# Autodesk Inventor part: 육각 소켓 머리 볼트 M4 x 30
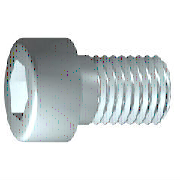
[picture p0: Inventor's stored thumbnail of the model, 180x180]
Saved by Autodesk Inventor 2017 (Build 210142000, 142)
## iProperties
IsCustomPart: 1
Created: 2012-02
Part Number: 육각 소켓 머리 볼트 M4 x 30
Material: 강철, 연강
Description: 원통형 머리 캡 나사
Document SubType Name: Modeling
Standard: JIS B 1176
Designer: mdu-01
Standards Organization: JIS
Language: ko-KR
Size Designation: M4 x 30
Categories: <MemberInstance><Categories><Category DisplayName="조임쇠" InternalName="e4da775c-781d-43d5-af7c-5136215cf5a6" Mnemonic="FSTN"><Category DisplayName="볼트" InternalN
Density: 1 g/cm^3
Appearance: 강철
Author: mdu-01
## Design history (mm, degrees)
sketch "스케치1"
  geometry: L1 (-1, 0)-(30, 0); L2 (30, 0)-(30, 2); L3 (30, 2)-(10, 2); L4 (10, 2)-(9.57, 2); L5 (9.57, 2)-(0, 2); L6 (0, 2)-(0, 3.5); L7 (0, 3.5)-(-4, 3.5); L8 (-4, 3.5)-(-4, 1.732); L9 (-4, 1.732)-(-2, 1.732); L10 (-2, 1.732)-(-1, 0); L11 (-10.8, 0)-(36.8, 0) reference; L12 (0, -0.7)-(0, 4.2) reference; L13 (10, 2)-(0, 2)
  constraints: 22 end point, 6 parallel, 2 collinear, 2 perpendicular, 1 horizontal, 1 point on line
  dimensions: "d1" = 20 distance from line of L3.end L2 (= GEL); "d2" = 0.42952 distance of L4.end L3.end (computed from GAL); "d3" = 4 distance between parallel lines of L8 L6 (= KOH); "d4" = 2 distance of L8.end L9.end (= INTI); "d5" = 60 deg angle of L10 L1; "d6" = 4 diameter of L3 L1 (= GD); "d7" = 4 diameter of L5 L1 (= BDM); "d8" = 3.4641 diameter of L9 L1 (= 1.1547 x SW); "d9" = 7 diameter of L7 L1 (= KOD); "d26" = 30 distance between parallel lines of L12 L2 (= NLG)
revolve "본체" sketch "스케치1" stored, may be unused: angle "d10" = 90 deg
sketch "스케치2"
  geometry: L1 (0, -4.9)-(0, 4.9) reference; L2 (-4.9, 0)-(4.9, 0) reference; L3 (1.732, 0)-(0.866, -1.5); L4 (0.866, -1.5)-(-0.866, -1.5); L5 (-0.866, -1.5)-(-1.732, 0); L6 (-1.732, 0)-(-0.866, 1.5); L7 (-0.866, 1.5)-(0.866, 1.5); L8 (0.866, 1.5)-(1.732, 0); 2 further points
  constraints: 12 end point, 1 coincident, 1 horizontal alignment, 1 point on line, 12 other
extrude "슬롯" join sketch "스케치2" stored distance "d11" = 10; taper "d12" = 0 deg
workplane "Work Plane1"
fillet "Fillet2" dims "d30" = 0.1 (= R)
body "Solid1"
fillet "모깎기1" dims "d17" = 0.4 (= RR)
feature "스레드" dims "d13" = 20 (= GEL), "d14" = 0
chamfer "모따기1" distance "d15" = 0.42941 (= -0.5 x SPD + 0.5 x GD); stored, may be unused: second distance "d16" = 0.42941 (= GUL), angle "d27" = 45 deg
other parameters: "GD" = 4 (= NND) [user parameter; used in 2 equation terms], "NLG" = 30 [user parameter; used in 1 equation term], "GEL" = 20 [user parameter; used in 2 equation terms], "KOD" = 7 [user parameter; used in 1 equation term], "KOH" = 4 [user parameter; used in 1 equation term], "INTI" = 2 [user parameter; used in 1 equation term], "GAL" = 0.42941 (= 0.61345 x PTC) [user parameter; used in 1 equation term], "GUL" = 0.42941 (= 0.61345 x PTC) [user parameter; used in 1 equation term], "BDM" = 4 (= NND) [user parameter; used in 1 equation term], "SW" = 3 [user parameter; used in 2 equation terms], "RR" = 0.4 [user parameter; used in 1 equation term], "SPD" = 3.14117 (= NND - 1.2269 x PTC) [user parameter; used in 1 equation term], "d19" = 0, "d28" = 0, "d29" = 0, "R" = 0.1 [user parameter; used in 1 equation term], "PHH" = 0.2 [user parameter], "GD1" = 3.14117 (= THREADDIA - 1.2269 x PTC) [user parameter], "THREADDIA" = 4 [user parameter; used in 1 equation term], "FAWI" = 45 deg [user parameter], "TPU" = 14.28571 (computed from PTC) [user parameter], "PTC" = 0.7 [user parameter; used in 5 equation terms], "NND" = 4 [user parameter; used in 3 equation terms], "TOA" = 30 deg [user parameter], "E0" = 3.465 (= 1.155 x SW) [user parameter]
